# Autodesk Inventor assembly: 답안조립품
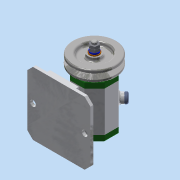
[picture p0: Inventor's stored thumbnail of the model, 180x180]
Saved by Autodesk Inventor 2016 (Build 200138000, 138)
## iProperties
Created: 2018-06
Part Number: 답안조립품
Material: 일반
Document SubType Name: Assembly
Designer: 605-03
Author: 605-03
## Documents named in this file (16)
- C:\Users\605-03\Desktop\480607V1002\답안조립품.iam
- C:\Users\605-03\Desktop\480607V1002\V벨트풀리.ipt
- C:\Users\605-03\Desktop\480607V1002\고무캡.ipt
- C:\Users\605-03\Desktop\480607V1002\너트 M8.ipt
- 너트 M8.ipt
- C:\Users\605-03\Desktop\480607V1002\뒤커버.ipt
- C:\Users\605-03\Desktop\480607V1002\베어링 15x32x9.ipt
- C:\Users\605-03\Desktop\480607V1002\본체.ipt
- C:\Users\605-03\Desktop\480607V1002\볼트 M4x12.ipt
- C:\Users\605-03\Desktop\480607V1002\스프링와셔 8.ipt
- C:\Users\605-03\Desktop\480607V1002\앞커버.ipt
- C:\Users\605-03\Desktop\480607V1002\오일 실 15 25 7.ipt
- C:\Users\605-03\Desktop\480607V1002\와셔 8x17.ipt
- C:\Users\605-03\Desktop\480607V1002\축.ipt
- C:\Users\605-03\Desktop\480607V1002\키 3x3x12.ipt
- 키 3x3x12.ipt
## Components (2 placed, 2 different names)
1. V벨트풀리:1 — 각도:2
2. 고무캡:1
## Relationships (1: Angle 1)
- 각도:2 [Angle]: V벨트풀리:1
